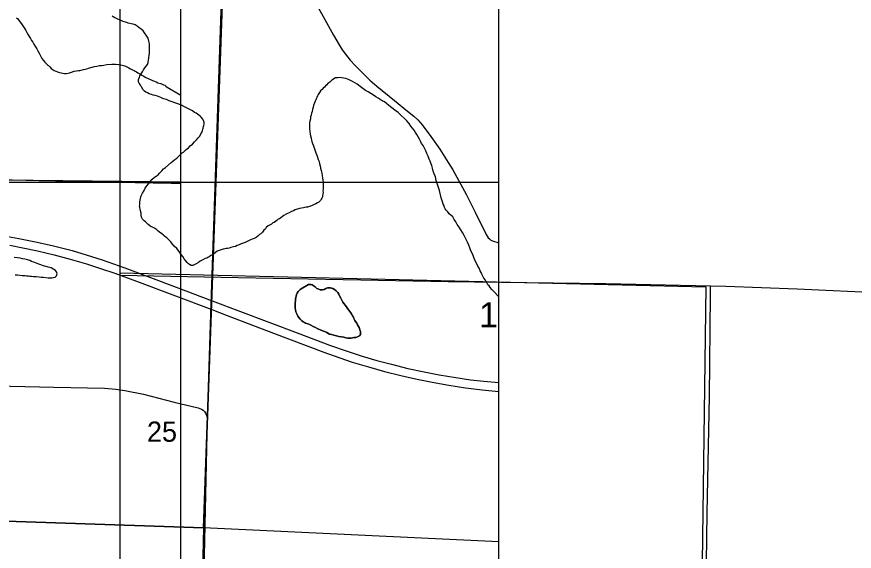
# Model space of a CAD drawing. Extents: x 0 to 68, y 0 to 52.9.
# Drawn here: x 49.292 to 51.122, y 36.457 to 37.625 of the extents above; entities that cross this region are included whole.
import ezdxf

# ---------------------------------------------------------------- set-up
doc = ezdxf.new("R2010")
doc.units = 0
for name, color, linetype in [('Default', 7, 'Continuous'), ('GM_X_County_Road', 7, 'Continuous'), ('GM_X_Minor_Lake', 7, 'Continuous'), ('GM_X_Minor_River', 7, 'Continuous'), ('GM_X_State_Route', 7, 'Continuous'), ('GM_X_Township', 7, 'Continuous'), ('GM_X_Township_Road', 7, 'Continuous')]:
    doc.layers.add(name, color=color, linetype=linetype)

msp = doc.modelspace()

# ---------------------------------------------------------------- linework, layer by layer
at = {"layer": 'Default'}
for p, q in [((49.5172, 34.4614), (49.5172, 52.9414)), ((50.3451, 32.7683), (50.3451, 42.0083)), ((49.6501, 31.1431), (49.6501, 38.5351)), ((41.1051, 37.2633), (50.3451, 37.2633))]:
    msp.add_line(p, q, dxfattribs=at)
for points in [[(48.4264, 37.8391), (49.7457, 37.7942), (49.6996, 36.5084), (48.3843, 36.5523)], [(48.3843, 36.5523), (49.6996, 36.5084), (49.6691, 35.1845), (48.3458, 35.227)]]:
    msp.add_lwpolyline(points, close=True, dxfattribs=at)
for points in [[(50.3451, 36.4776), (49.6996, 36.5084), (49.7457, 37.7942), (50.3451, 37.7786)], [(49.5419, 37.6098), (49.5384, 37.6108), (49.5354, 37.6113), (49.5324, 37.6123), (49.5289, 37.6133), (49.5244, 37.6149), (49.5214, 37.6164), (49.5179, 37.6179), (49.5139, 37.6194), (49.5094, 37.6214), (49.5059, 37.623), (49.5023, 37.625), (49.4998, 37.627)], [(49.5697, 37.2455), (49.5722, 37.2505), (49.5762, 37.2555), (49.5803, 37.261), (49.5868, 37.2695), (49.5923, 37.2745), (49.5964, 37.277), (49.6004, 37.28), (49.6034, 37.283), (49.6059, 37.2855), (49.6089, 37.2885), (49.6125, 37.2925), (49.6165, 37.296), (49.629, 37.3065), (49.6336, 37.31), (49.6371, 37.313), (49.6411, 37.316), (49.6436, 37.3185), (49.6466, 37.3215), (49.6502, 37.325), (49.6532, 37.3275), (49.6562, 37.3295), (49.6587, 37.332), (49.6617, 37.335), (49.6668, 37.339), (49.6708, 37.343), (49.6758, 37.347), (49.6798, 37.3515), (49.6844, 37.356), (49.6879, 37.3605), (49.6914, 37.3645), (49.6939, 37.369), (49.6959, 37.372), (49.6974, 37.3765), (49.698, 37.3795), (49.699, 37.382), (49.6995, 37.385), (49.7005, 37.3875), (49.701, 37.3901), (49.7015, 37.3941), (49.7, 37.3981), (49.698, 37.4011), (49.6945, 37.4056), (49.6925, 37.4081), (49.6895, 37.4102), (49.6865, 37.4122), (49.6835, 37.4142), (49.68, 37.4162), (49.676, 37.4197), (49.6695, 37.4228), (49.6639, 37.4253), (49.6579, 37.4283), (49.6514, 37.4319), (49.6309, 37.4394), (49.6248, 37.4415), (49.6188, 37.444), (49.6123, 37.446), (49.6063, 37.4486), (49.5988, 37.4516), (49.5938, 37.4531), (49.5898, 37.4541), (49.5857, 37.4551), (49.5812, 37.4567), (49.5772, 37.4587), (49.5737, 37.4607), (49.5707, 37.4627), (49.5672, 37.4662), (49.5647, 37.4713), (49.5627, 37.4738), (49.5612, 37.4768), (49.5592, 37.4803), (49.5577, 37.4833), (49.5577, 37.4883), (49.5597, 37.4928), (49.5607, 37.4959), (49.5628, 37.4994), (49.5648, 37.5024), (49.5668, 37.5059), (49.5688, 37.5094), (49.5718, 37.5134), (49.5743, 37.5169), (49.5774, 37.5209), (49.5784, 37.5254), (49.5794, 37.5309), (49.5799, 37.5339), (49.5804, 37.5364), (49.5809, 37.5404), (49.5814, 37.5455), (49.5814, 37.551), (49.582, 37.556), (49.582, 37.561), (49.5815, 37.566), (49.5805, 37.572), (49.5785, 37.5786), (49.5675, 37.5947), (49.5635, 37.5982), (49.559, 37.6012), (49.5545, 37.6047), (49.55, 37.6073), (49.546, 37.6088), (49.5419, 37.6098)], [(50.0654, 37.4571), (50.0599, 37.4611), (50.0539, 37.4642), (50.0479, 37.4687), (50.0419, 37.4727), (50.0354, 37.4778), (50.0253, 37.4838), (50.0178, 37.4873), (50.0108, 37.4899), (49.9973, 37.4924), (49.9932, 37.4919), (49.9907, 37.4914), (49.9882, 37.4915), (49.9847, 37.4895), (49.9817, 37.4875), (49.9792, 37.4855), (49.9757, 37.4825), (49.9716, 37.479), (49.9696, 37.4765), (49.9666, 37.474), (49.9641, 37.4715), (49.9616, 37.469), (49.9591, 37.4665), (49.9555, 37.463), (49.953, 37.4595), (49.9505, 37.4555), (49.949, 37.4525), (49.9475, 37.4489), (49.946, 37.4459), (49.945, 37.4434), (49.944, 37.4409), (49.9424, 37.4369), (49.9404, 37.4314), (49.9394, 37.4279), (49.9379, 37.4224), (49.9374, 37.4184), (49.9359, 37.4144), (49.9349, 37.4104), (49.9338, 37.4064), (49.9333, 37.4023), (49.9318, 37.3973), (49.9313, 37.3933), (49.9313, 37.3893), (49.9313, 37.3863), (49.9313, 37.3838), (49.9313, 37.3803), (49.9327, 37.3687), (49.9337, 37.3647), (49.9347, 37.3597), (49.9357, 37.3557), (49.9367, 37.3527), (49.9382, 37.3481), (49.9402, 37.3431), (49.9417, 37.3386), (49.9432, 37.3341), (49.9452, 37.3281), (49.9472, 37.3225), (49.9487, 37.318), (49.9507, 37.313), (49.9522, 37.3085), (49.9532, 37.304), (49.9547, 37.2994), (49.9557, 37.2939), (49.9571, 37.2889), (49.9581, 37.2834), (49.9591, 37.2773), (49.9601, 37.2728), (49.9606, 37.2678), (49.9611, 37.2638), (49.9611, 37.2588), (49.9611, 37.2538), (49.9611, 37.2487), (49.9606, 37.2447), (49.9611, 37.2417), (49.9605, 37.2377), (49.96, 37.2347), (49.9595, 37.2317), (49.9585, 37.2287), (49.957, 37.2262), (49.9555, 37.2232), (49.952, 37.2197), (49.949, 37.2182), (49.9449, 37.2162), (49.9404, 37.2142), (49.9359, 37.2122), (49.9314, 37.2102), (49.9269, 37.2092), (49.9238, 37.2087), (49.9183, 37.2077), (49.9138, 37.2068), (49.9093, 37.2058), (49.9002, 37.2028), (49.8962, 37.2013), (49.8917, 37.1993), (49.8867, 37.1968), (49.8832, 37.1953), (49.8802, 37.1938), (49.8756, 37.1908), (49.8726, 37.1888), (49.8691, 37.1858), (49.8656, 37.1838)], [(50.3451, 37.0128), (50.3338, 37.0253), (50.3298, 37.0293), (50.3263, 37.0334), (50.3238, 37.0369), (50.3213, 37.0394), (50.3188, 37.0434), (50.3173, 37.0464), (50.3158, 37.0494), (50.3128, 37.054), (50.3103, 37.058), (50.3078, 37.0625), (50.3063, 37.066), (50.3043, 37.0695), (50.3023, 37.0756), (50.2993, 37.0801), (50.2968, 37.0851), (50.2943, 37.0901), (50.2923, 37.0952), (50.2909, 37.0992), (50.2889, 37.1032), (50.2869, 37.1082), (50.2844, 37.1138), (50.2819, 37.1198), (50.2794, 37.1258), (50.2769, 37.1323), (50.2724, 37.1409), (50.2694, 37.1474), (50.2659, 37.1534), (50.2619, 37.1595), (50.2584, 37.1655), (50.2544, 37.171), (50.2509, 37.1766), (50.2474, 37.1821), (50.2444, 37.1876), (50.2404, 37.1917), (50.2369, 37.1947), (50.2339, 37.1987), (50.2299, 37.2022), (50.2279, 37.2057), (50.2264, 37.2083), (50.2254, 37.2118), (50.2234, 37.2158), (50.2219, 37.2203), (50.2204, 37.2248), (50.2194, 37.2293), (50.2154, 37.2454), (50.2124, 37.254), (50.2105, 37.2605), (50.2085, 37.2675), (50.2065, 37.275), (50.204, 37.2816), (50.202, 37.2876), (50.2, 37.2946), (50.1985, 37.3002), (50.1965, 37.3052), (50.195, 37.3092), (50.193, 37.3137), (50.191, 37.3202), (50.188, 37.3263), (50.1855, 37.3323), (50.1825, 37.3378), (50.1795, 37.3439), (50.1765, 37.3484), (50.174, 37.3534), (50.1715, 37.3579), (50.169, 37.363), (50.166, 37.368), (50.1631, 37.3725), (50.16, 37.377), (50.1565, 37.3816), (50.153, 37.3861), (50.1495, 37.3916), (50.1445, 37.3976), (50.138, 37.4037), (50.1315, 37.4097), (50.125, 37.4158), (50.118, 37.4208), (50.1115, 37.4258), (50.105, 37.4314), (50.0995, 37.4354), (50.095, 37.4394), (50.09, 37.4415), (50.086, 37.4445), (50.0814, 37.4475), (50.0764, 37.4505), (50.0714, 37.4536), (50.0654, 37.4571)], [(49.6501, 36.2035), (49.1852, 36.2124), (49.1976, 37.2693), (49.6501, 37.2645)], [(49.8656, 37.1838), (49.8631, 37.1828), (49.8601, 37.1798), (49.857, 37.1773), (49.854, 37.1753), (49.8515, 37.1744), (49.848, 37.1719), (49.844, 37.1699), (49.841, 37.1679), (49.8369, 37.1644), (49.8349, 37.1619), (49.8319, 37.1584), (49.8284, 37.1544), (49.8249, 37.1509), (49.8224, 37.1494), (49.8183, 37.1459), (49.8148, 37.1429), (49.8103, 37.1404), (49.8063, 37.1389), (49.8023, 37.1374), (49.7992, 37.1359), (49.7952, 37.1339), (49.7907, 37.1319), (49.7862, 37.1304), (49.7817, 37.1289), (49.7776, 37.1269), (49.7736, 37.1249), (49.7696, 37.123), (49.7656, 37.122), (49.7626, 37.1215), (49.7591, 37.1205), (49.7556, 37.1195), (49.7525, 37.119), (49.7495, 37.1185), (49.7465, 37.118), (49.7425, 37.117), (49.734, 37.114), (49.7294, 37.1125), (49.7249, 37.1091), (49.7224, 37.1071), (49.7194, 37.1046), (49.7159, 37.1031), (49.7119, 37.1006), (49.7093, 37.0991), (49.7068, 37.0976), (49.7033, 37.0966), (49.6983, 37.0941), (49.6953, 37.0926), (49.6923, 37.0911), (49.6888, 37.0881), (49.6837, 37.0851), (49.6792, 37.0826), (49.6762, 37.0816), (49.6727, 37.0816), (49.6692, 37.0836), (49.6667, 37.0852), (49.6637, 37.0877), (49.6612, 37.0917), (49.6577, 37.0957), (49.6542, 37.1008), (49.6502, 37.1063), (49.6462, 37.1123), (49.6417, 37.1189), (49.6356, 37.1234), (49.6321, 37.1284), (49.6281, 37.1329), (49.6246, 37.1365), (49.6216, 37.1395), (49.6196, 37.142), (49.6171, 37.1435), (49.6146, 37.1455), (49.6121, 37.148), (49.6086, 37.1506), (49.6036, 37.1546), (49.6001, 37.1576), (49.5971, 37.1601), (49.5926, 37.1632), (49.5881, 37.1652), (49.5851, 37.1662), (49.5816, 37.1692), (49.5786, 37.1712), (49.5761, 37.1742), (49.5731, 37.1768), (49.57, 37.1788), (49.5665, 37.1828), (49.5645, 37.1873), (49.5636, 37.1908), (49.5631, 37.1959), (49.5621, 37.2009), (49.5611, 37.2049), (49.5606, 37.2089), (49.5601, 37.2114), (49.5606, 37.2144), (49.5606, 37.2169), (49.5606, 37.2204), (49.5611, 37.2245), (49.5621, 37.228), (49.5626, 37.2315), (49.5637, 37.234), (49.5662, 37.2395), (49.5697, 37.2455)], [(49.5172, 37.0651), (50.798, 37.0352), (50.7632, 34.4614)]]:
    msp.add_lwpolyline(points, dxfattribs=at)
at = {"layer": 'GM_X_County_Road'}
for points in [[(49.5172, 37.06), (49.7752, 37.0553), (50.2346, 37.0466), (50.5792, 37.0423), (50.8081, 37.037)], [(50.8081, 37.037), (50.8417, 37.0362), (50.9975, 37.0302), (51.1859, 37.0214), (51.2351, 37.0199), (51.4672, 37.0095)], [(49.0484, 36.8262), (49.065, 36.8251), (49.1716, 36.8208), (49.2782, 36.8175), (49.3725, 36.8159), (49.4833, 36.8133), (49.5078, 36.8115), (49.5281, 36.8085), (49.5683, 36.8), (49.6359, 36.7831), (49.6878, 36.7704), (49.6954, 36.7674), (49.6989, 36.7651), (49.7018, 36.7624), (49.7043, 36.7588)], [(49.7043, 36.7588), (49.7064, 36.7539), (49.7076, 36.7476), (49.7078, 36.7352), (49.705, 36.6326), (49.7014, 36.4644), (49.6969, 36.247), (49.6952, 36.1873), (49.6951, 36.1812)]]:
    msp.add_lwpolyline(points, dxfattribs=at)
at = {"layer": 'GM_X_Minor_Lake'}
for points in [[(49.2883, 37.0613), (49.2933, 37.0608), (49.2983, 37.0603), (49.3033, 37.0598), (49.3089, 37.0597), (49.3129, 37.0592), (49.3169, 37.0587), (49.3204, 37.0582), (49.3239, 37.0582), (49.3284, 37.0577), (49.3339, 37.0577), (49.3405, 37.0566), (49.345, 37.0561), (49.349, 37.0561), (49.3605, 37.0546), (49.3635, 37.0545), (49.3681, 37.0545), (49.3716, 37.055), (49.3756, 37.056), (49.3786, 37.059), (49.3796, 37.064), (49.3786, 37.0675), (49.3761, 37.0706), (49.3726, 37.0731), (49.3666, 37.0761), (49.3636, 37.0771), (49.3601, 37.0781), (49.3561, 37.0792), (49.3521, 37.0802), (49.348, 37.0817), (49.3445, 37.0832), (49.34, 37.0847), (49.3365, 37.0857), (49.3325, 37.0873), (49.3285, 37.0888), (49.324, 37.0903), (49.32, 37.0923), (49.315, 37.0938), (49.3094, 37.0954), (49.3039, 37.0964), (49.2989, 37.0974), (49.2934, 37.0979), (49.2859, 37.0989)], [(49.929, 37.0402), (49.9134, 37.0307), (49.9109, 37.0292), (49.9069, 37.0247), (49.9043, 37.0207), (49.9033, 37.0182), (49.9023, 37.0147), (49.9018, 37.0117), (49.9008, 37.0081), (49.9008, 37.0041), (49.9003, 37.0001), (49.8998, 36.9971), (49.8998, 36.9926), (49.8998, 36.9891), (49.9007, 36.9846), (49.9017, 36.9801), (49.9037, 36.9755), (49.9057, 36.971), (49.9082, 36.9675), (49.9107, 36.964), (49.9142, 36.961), (49.9172, 36.9584), (49.9202, 36.9569), (49.9228, 36.9554), (49.9258, 36.9544), (49.9298, 36.9529), (49.9343, 36.9509), (49.9393, 36.9483), (49.9443, 36.9458), (49.9498, 36.9433), (49.9694, 36.9347), (49.9749, 36.9317), (49.9794, 36.9306), (49.9849, 36.9291), (49.9904, 36.9276), (49.9954, 36.9266), (50.0015, 36.9256), (50.0065, 36.9245), (50.011, 36.9235), (50.015, 36.9225), (50.0185, 36.923), (50.0225, 36.923), (50.0255, 36.9235), (50.0285, 36.924), (50.0326, 36.9244), (50.0361, 36.9254), (50.0406, 36.9279)], [(49.929, 37.0402), (49.932, 37.0402), (49.934, 37.0396), (49.937, 37.0391), (49.9395, 37.0376), (49.9435, 37.0346), (49.9475, 37.0311), (49.9515, 37.0296), (49.9545, 37.0285), (49.9575, 37.0285), (49.9601, 37.0285), (49.9631, 37.029), (49.9671, 37.031), (49.9711, 37.0325), (49.9746, 37.0325), (49.9771, 37.0325), (49.9796, 37.032), (49.9821, 37.0315), (49.9861, 37.0289), (49.9897, 37.0264), (49.9932, 37.0224), (49.9952, 37.0189), (49.9961, 37.0164), (49.9996, 37.0098), (50.0011, 37.0073), (50.0046, 37.0013), (50.0121, 36.9912), (50.0146, 36.9877), (50.0171, 36.9842), (50.0196, 36.9807), (50.0216, 36.9777), (50.0236, 36.9741), (50.0256, 36.9711), (50.0276, 36.9686), (50.0286, 36.9656), (50.0306, 36.9616), (50.0321, 36.9591), (50.0346, 36.9555), (50.0366, 36.952), (50.0386, 36.9485), (50.0396, 36.946), (50.0416, 36.941), (50.0431, 36.9375), (50.0431, 36.9339), (50.0426, 36.9309), (50.0406, 36.9279), (50.0361, 36.9254), (50.0326, 36.9244), (50.0285, 36.924), (50.0255, 36.9235), (50.0225, 36.923), (50.0185, 36.923), (50.015, 36.9225), (50.011, 36.9235), (50.0065, 36.9245), (50.0015, 36.9256), (49.9954, 36.9266), (49.9904, 36.9276), (49.9849, 36.9291), (49.9794, 36.9306), (49.9749, 36.9317), (49.9694, 36.9347), (49.9498, 36.9433), (49.9443, 36.9458), (49.9393, 36.9483), (49.9343, 36.9509), (49.9298, 36.9529), (49.9258, 36.9544), (49.9228, 36.9554), (49.9202, 36.9569), (49.9172, 36.9584), (49.9142, 36.961), (49.9107, 36.964), (49.9082, 36.9675), (49.9057, 36.971), (49.9037, 36.9755), (49.9017, 36.9801), (49.9007, 36.9846), (49.8998, 36.9891), (49.8998, 36.9926), (49.8998, 36.9971), (49.9003, 37.0001), (49.9008, 37.0041), (49.9008, 37.0081), (49.9018, 37.0117), (49.9023, 37.0147), (49.9033, 37.0182), (49.9043, 37.0207), (49.9069, 37.0247), (49.9109, 37.0292), (49.9134, 37.0307), (49.929, 37.0402)], [(50.0406, 36.9279), (50.0426, 36.9309), (50.0431, 36.9339), (50.0431, 36.9375), (50.0416, 36.941), (50.0396, 36.946), (50.0386, 36.9485), (50.0366, 36.952), (50.0346, 36.9555), (50.0321, 36.9591), (50.0306, 36.9616), (50.0286, 36.9656), (50.0276, 36.9686), (50.0256, 36.9711), (50.0236, 36.9741), (50.0216, 36.9777), (50.0196, 36.9807), (50.0171, 36.9842), (50.0146, 36.9877), (50.0121, 36.9912), (50.0046, 37.0013), (50.0011, 37.0073), (49.9996, 37.0098), (49.9961, 37.0164), (49.9952, 37.0189), (49.9932, 37.0224), (49.9897, 37.0264), (49.9861, 37.0289), (49.9821, 37.0315), (49.9796, 37.032), (49.9771, 37.0325), (49.9746, 37.0325), (49.9711, 37.0325), (49.9671, 37.031), (49.9631, 37.029), (49.9601, 37.0285), (49.9575, 37.0285), (49.9545, 37.0285), (49.9515, 37.0296), (49.9475, 37.0311), (49.9435, 37.0346), (49.9395, 37.0376), (49.937, 37.0391), (49.934, 37.0396), (49.932, 37.0402), (49.929, 37.0402)]]:
    msp.add_lwpolyline(points, dxfattribs=at)
at = {"layer": 'GM_X_Minor_River'}
for points in [[(49.2913, 37.6229), (49.2937, 37.6205), (49.2957, 37.6184), (49.3032, 37.6079), (49.3063, 37.6034), (49.3091, 37.599), (49.3115, 37.5949), (49.3138, 37.5905), (49.3162, 37.586), (49.3186, 37.582), (49.3213, 37.5775), (49.3241, 37.5731), (49.3269, 37.5694), (49.3292, 37.5654), (49.3328, 37.5593), (49.3351, 37.5552), (49.3375, 37.5508), (49.3403, 37.5455), (49.3434, 37.5399), (49.3466, 37.5342), (49.3497, 37.5297), (49.3529, 37.5261), (49.3557, 37.5228), (49.3585, 37.52), (49.3609, 37.5183), (49.3636, 37.5155), (49.3664, 37.5122), (49.3688, 37.5106), (49.3712, 37.509), (49.3736, 37.5077), (49.3768, 37.5061), (49.3808, 37.5048), (49.3848, 37.5036), (49.3889, 37.5023), (49.3921, 37.5019), (49.3957, 37.5014), (49.4001, 37.5014), (49.4038, 37.5021), (49.407, 37.5029), (49.4114, 37.5044), (49.4171, 37.506), (49.4219, 37.5067), (49.4264, 37.5074), (49.4296, 37.5078), (49.4324, 37.5086), (49.4377, 37.5097), (49.4413, 37.5105), (49.4446, 37.5116), (49.4482, 37.5128), (49.4615, 37.5162), (49.4668, 37.5174), (49.4721, 37.5185), (49.4769, 37.5188), (49.4821, 37.5196), (49.4886, 37.5207), (49.4991, 37.5218), (49.5035, 37.5217), (49.5075, 37.5216), (49.5148, 37.5207), (49.5188, 37.5203), (49.5248, 37.5186), (49.5276, 37.5178), (49.5308, 37.5161), (49.5336, 37.5153), (49.5368, 37.5136), (49.5404, 37.5116), (49.5448, 37.5091), (49.5481, 37.5075), (49.5505, 37.5062)], [(49.5505, 37.5062), (49.5529, 37.505), (49.5565, 37.5029), (49.5588, 37.5013), (49.5621, 37.4996), (49.5652, 37.4976), (49.5692, 37.4951), (49.572, 37.4935), (49.5748, 37.4918), (49.5776, 37.4906), (49.5805, 37.4893), (49.5841, 37.4877), (49.5885, 37.486), (49.5929, 37.4844), (49.5965, 37.4827), (49.6001, 37.4811), (49.6065, 37.479), (49.6121, 37.4765), (49.6149, 37.4756), (49.6177, 37.4736), (49.6205, 37.4715), (49.6501, 37.4538)]]:
    msp.add_lwpolyline(points, dxfattribs=at)
at = {"layer": 'GM_X_State_Route'}
for points in [[(49.2559, 37.1478), (49.2964, 37.1408), (49.3326, 37.1335), (49.3687, 37.1252), (49.4125, 37.114), (49.443, 37.1049), (49.4781, 37.0937), (49.5277, 37.0766), (49.64, 37.0343), (49.7188, 37.0045), (49.9041, 36.9344), (49.977, 36.9067), (50.0112, 36.8946), (50.0468, 36.8834), (50.0787, 36.8741), (50.1104, 36.8655), (50.1463, 36.8567), (50.1824, 36.8488), (50.2147, 36.8426), (50.2511, 36.8366), (50.2836, 36.8319), (50.3122, 36.8285), (50.3451, 36.8254)], [(49.2763, 37.1258), (49.3047, 37.1201), (49.3367, 37.1134), (49.3733, 37.1048), (49.4083, 37.0956), (49.4443, 37.0853), (49.4749, 37.0751), (49.5062, 37.0645), (49.5536, 37.0471), (49.718, 36.985), (49.7515, 36.9723), (49.8525, 36.9339), (49.9629, 36.8921), (49.9974, 36.8794), (50.0246, 36.8704), (50.06, 36.8598), (50.0955, 36.8499), (50.1313, 36.8409), (50.1632, 36.8336), (50.1994, 36.8262), (50.2357, 36.8198), (50.2722, 36.8144), (50.3088, 36.8099), (50.3451, 36.8063)]]:
    msp.add_lwpolyline(points, dxfattribs=at)
at = {"layer": 'GM_X_Township'}
msp.add_lwpolyline([(44.7776, 37.9316), (45.7636, 37.9078), (45.7815, 37.9075), (46.4354, 37.887), (47.0934, 37.8749), (47.9758, 37.8521), (48.4292, 37.8378), (49.0919, 37.8129), (49.7424, 37.7891), (49.7157, 36.9972), (49.7077, 36.748), (49.6951, 36.1805), (49.6872, 35.8521), (49.6545, 34.5254), (49.6326, 33.8658), (49.6189, 33.2067), (49.6098, 32.7683)], dxfattribs=at)
at = {"layer": 'GM_X_Township_Road'}
for points in [[(49.9385, 37.6675), (49.984, 37.5848), (49.9962, 37.5635), (50.0028, 37.5532), (50.01, 37.5433), (50.0203, 37.5306), (50.0312, 37.5184), (50.0455, 37.5038), (50.0634, 37.4869), (50.0788, 37.4734), (50.1169, 37.4423), (50.1457, 37.4191), (50.1595, 37.4077), (50.1679, 37.4), (50.1785, 37.3879), (50.1802, 37.3858), (50.1968, 37.3634), (50.2161, 37.3356), (50.2345, 37.3068), (50.2446, 37.2903), (50.2743, 37.2358), (50.2934, 37.1979), (50.3175, 37.149), (50.3196, 37.1455), (50.3219, 37.1423), (50.3246, 37.1395), (50.3277, 37.1372), (50.3311, 37.1355), (50.3451, 37.131)], [(49.197, 37.2706), (49.2518, 37.2695), (49.3403, 37.2672), (49.4486, 37.2652), (49.488, 37.264), (49.5503, 37.2628), (49.629, 37.2611), (49.6501, 37.2607)], [(50.7869, 35.5244), (50.7876, 35.6147), (50.7905, 35.7869), (50.7935, 36.0247), (50.7957, 36.1887), (50.7978, 36.3445), (50.7981, 36.3773), (50.8008, 36.5412), (50.8059, 36.7954), (50.8079, 37.0168), (50.8081, 37.037)]]:
    msp.add_lwpolyline(points, dxfattribs=at)

# ---------------------------------------------------------------- texts
at = {"layer": 'Default'}
for s, height, p in [('1', 0.0553, (50.3023, 36.946)), ('25', 0.0442, (49.5761, 36.6962))]:
    msp.add_text(s, height=height, rotation=0, dxfattribs=at).set_placement(p)

doc.saveas('drawing.dxf')
